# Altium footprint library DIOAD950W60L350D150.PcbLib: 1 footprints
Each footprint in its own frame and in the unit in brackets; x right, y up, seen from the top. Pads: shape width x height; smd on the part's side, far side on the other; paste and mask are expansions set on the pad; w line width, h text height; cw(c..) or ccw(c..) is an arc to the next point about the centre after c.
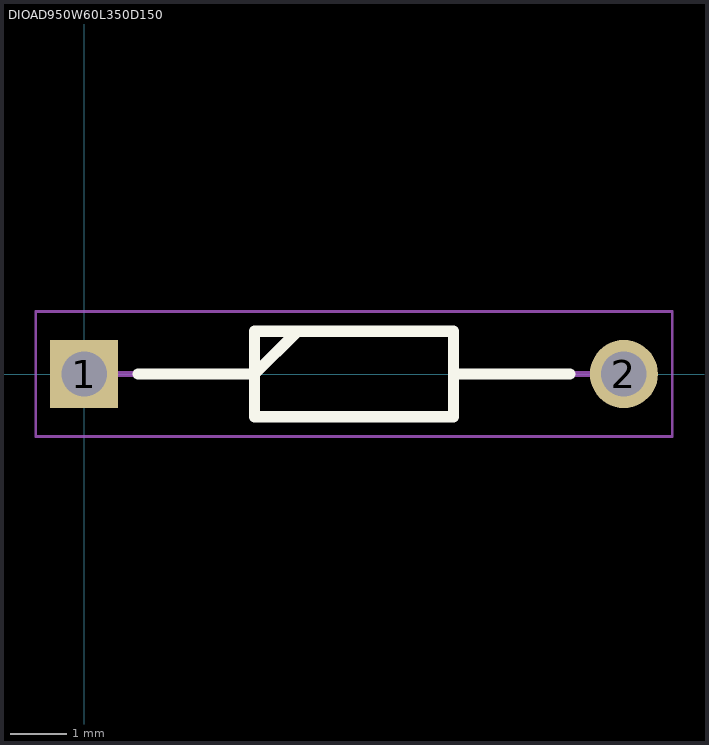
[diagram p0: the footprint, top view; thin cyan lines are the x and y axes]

## DIOAD950W60L350D150 [mm]
pads (2):
  rect 1.2x1.2 / inner round 1.2 / far side rect 1.2x1.2 hole 0.8: 1(0,0)
  round 1.2 hole 0.8: 2(9.5,0)
Top Overlay:
  lines w0.2: 0.95,0 3,0 3.75,0.75 ; 6.5,0 8.55,0 ; 3,-0.75 6.5,-0.75 6.5,0.75 3,0.75 3,-0.75
Mechanical 15:
  lines w0.1: 0,0 3,0 3.75,0.75 ; 6.5,0 9.5,0 ; 3,-0.75 6.5,-0.75 6.5,0.75 3,0.75 3,-0.75
Mechanical 20:
  lines w0.05: -0.85,-1.1 10.35,-1.1 10.35,1.1 -0.85,1.1 -0.85,-1.1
